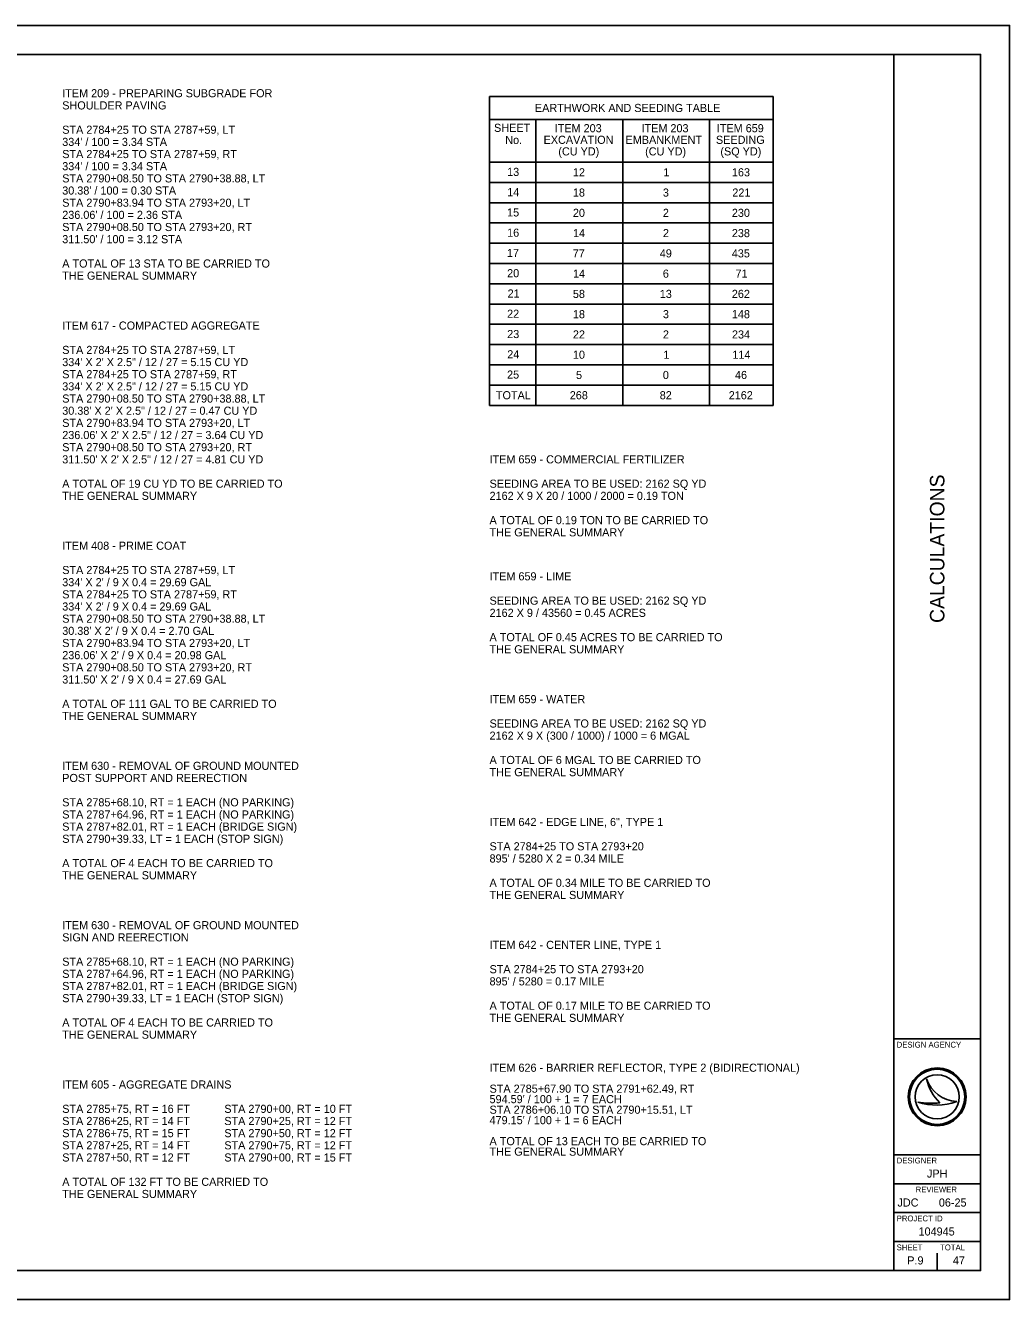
# Model space of a CAD drawing. Extents: x 0 to 34, y 0 to 22.
# Drawn here: x 17 to 34, y 0 to 22 of the extents above; entities that cross this region are included whole.
import ezdxf

# ---------------------------------------------------------------- set-up
doc = ezdxf.new("R2010")
doc.units = 0
for name, color, linetype in [('SH_Border', 7, 'Continuous'), ('SH_Cut_Line', 7, 'Continuous'), ('SH_Data', 7, 'Continuous'), ('TX_P_1', 7, 'Continuous')]:
    doc.layers.add(name, color=color, linetype=linetype)

msp = doc.modelspace()

# ---------------------------------------------------------------- linework, layer by layer
at = {"layer": 'SH_Border'}
for p, q in [((32, 0.5), (32, 21.5)), ((32, 4.5), (33.5, 4.5)), ((32, 2.5), (33.5, 2.5)), ((32, 2), (33.5, 2)), ((32, 1.5), (33.5, 1.5)), ((32, 1), (33.5, 1))]:
    msp.add_line(p, q, dxfattribs=at)
msp.add_lwpolyline([(1.5, 21.5), (33.5, 21.5), (33.5, 0.5), (1.5, 0.5)], close=True, dxfattribs=at)
at = {"layer": 'SH_Cut_Line'}
msp.add_lwpolyline([(0, 0), (34, 0), (34, 22), (0, 22)], close=True, dxfattribs=at)
at = {"layer": 'SH_Data'}
for p, q in [((32.567, 3.81), (32.567, 3.81)), ((32.417, 3.41), (32.417, 3.41)), ((32.75, 3.5), (32.75, 3.5)), ((33.087, 3.419), (33.087, 3.419)), ((32.375, 0.675), (32.375, 0.675)), ((32.75, 0.5), (32.75, 0.8))]:
    msp.add_line(p, q, dxfattribs=at)
for radius in [0.5, 0.477, 0.477, 0.382]:
    msp.add_circle((32.75, 3.5), radius, dxfattribs=at)
for centre, radius, start, end in [((33.116, 3.998), 0.58, 198.9257, 198.9319), ((33.347, 3.97), 0.796, 191.6379, 191.6421), ((33.116, 3.998), 0.58, 198.9319, 267.1657), ((33.347, 3.97), 0.796, 191.6421, 226.0947), ((32.739, 4.37), 1.013, 251.4576, 290.0832), ((32.648, 4.654), 1.266, 259.4964, 259.4995), ((32.739, 4.37), 1.013, 251.4527, 251.4576), ((32.648, 4.654), 1.266, 259.4995, 276.6672)]:
    msp.add_arc(centre, radius, start, end, dxfattribs=at)
at = {"layer": 'TX_P_1'}
for p, q in [((29.917, 20.776), (25.017, 20.776)), ((25.017, 20.776), (25.017, 15.44)), ((29.917, 20.776), (29.917, 15.44)), ((29.917, 20.376), (25.017, 20.376)), ((25.817, 20.376), (25.817, 15.44)), ((27.317, 20.376), (27.317, 15.44)), ((28.817, 20.376), (28.817, 15.44)), ((29.917, 19.64), (25.017, 19.64)), ((29.917, 19.29), (25.017, 19.29)), ((29.917, 18.94), (25.017, 18.94)), ((29.917, 18.59), (25.017, 18.59)), ((29.917, 18.24), (25.017, 18.24)), ((29.917, 17.89), (25.017, 17.89)), ((29.917, 17.54), (25.017, 17.54)), ((29.917, 17.19), (25.017, 17.19)), ((29.917, 16.84), (25.017, 16.84)), ((29.917, 16.49), (25.017, 16.49)), ((29.917, 16.14), (25.017, 16.14)), ((29.917, 15.79), (25.017, 15.79)), ((29.917, 15.44), (25.017, 15.44))]:
    msp.add_line(p, q, dxfattribs=at)

# ---------------------------------------------------------------- texts
at = {"layer": 'SH_Data'}
msp.add_text('CALCULATIONS', height=0.25, rotation=90, dxfattribs=at).set_placement((32.875, 11.683))
for s, height, p in [('DESIGN AGENCY', 0.1, (32.05, 4.35)), ('DESIGNER', 0.1, (32.05, 2.35)), ('JPH', 0.14, (32.573, 2.105)), ('REVIEWER', 0.1, (32.378, 1.85)), ('JDC', 0.14, (32.064, 1.605)), ('06-25', 0.14, (32.779, 1.605)), ('PROJECT ID', 0.1, (32.05, 1.35)), ('104945', 0.14, (32.428, 1.105)), ('SHEET', 0.1, (32.05, 0.85)), ('TOTAL', 0.1, (32.8, 0.85)), ('P.9', 0.14, (32.233, 0.605)), ('47', 0.14, (33.021, 0.605))]:
    msp.add_text(s, height=height, dxfattribs=at).set_placement(p)
at = {"layer": 'TX_P_1'}
for s, p in [('ITEM 209 - PREPARING SUBGRADE FOR', (17.635, 20.76)), ('SHOULDER PAVING', (17.635, 20.55)), ('EARTHWORK AND SEEDING TABLE', (25.801, 20.506)), ('STA 2784+25 TO STA 2787+59, LT', (17.635, 20.13)), ('SHEET', (25.095, 20.163)), ('ITEM 203', (26.143, 20.156)), ('ITEM 203', (27.643, 20.156)), ('ITEM 659', (28.943, 20.156)), ("334' / 100 = 3.34 STA", (17.635, 19.92)), ('No.', (25.288, 19.953)), ('EXCAVATION', (25.951, 19.956)), ('EMBANKMENT', (27.367, 19.956)), ('SEEDING', (28.928, 19.956)), ('STA 2784+25 TO STA 2787+59, RT', (17.635, 19.71)), ('(CU YD)', (26.205, 19.756)), ('(CU YD)', (27.705, 19.756)), ('(SQ YD)', (29.005, 19.756)), ("334' / 100 = 3.34 STA", (17.635, 19.5)), ('STA 2790+08.50 TO STA 2790+38.88, LT', (17.635, 19.29)), ('13', (25.321, 19.402)), ('12', (26.457, 19.395)), ('1', (28.02, 19.395)), ('163', (29.204, 19.395)), ("30.38' / 100 = 0.30 STA", (17.635, 19.08)), ('14', (25.322, 19.052)), ('18', (26.457, 19.045)), ('3', (28.012, 19.045)), ('221', (29.211, 19.045)), ('STA 2790+83.94 TO STA 2793+20, LT', (17.635, 18.87)), ("236.06' / 100 = 2.36 STA", (17.635, 18.66)), ('15', (25.32, 18.702)), ('20', (26.457, 18.695)), ('2', (28.011, 18.695)), ('230', (29.203, 18.695)), ('STA 2790+08.50 TO STA 2793+20, RT', (17.635, 18.45)), ('16', (25.321, 18.352)), ('14', (26.459, 18.345)), ('2', (28.012, 18.345)), ('238', (29.203, 18.345)), ("311.50' / 100 = 3.12 STA", (17.635, 18.24)), ('17', (25.318, 18.002)), ('77', (26.454, 17.995)), ('49', (27.958, 17.995)), ('435', (29.202, 17.995)), ('A TOTAL OF 13 STA TO BE CARRIED TO', (17.635, 17.82)), ('THE GENERAL SUMMARY', (17.635, 17.61)), ('20', (25.321, 17.652)), ('14', (26.459, 17.645)), ('6', (28.011, 17.645)), ('71', (29.266, 17.645)), ('21', (25.329, 17.302)), ('58', (26.457, 17.295)), ('13', (27.958, 17.295)), ('262', (29.203, 17.295)), ('22', (25.321, 16.952)), ('18', (26.457, 16.945)), ('3', (28.012, 16.945)), ('148', (29.203, 16.945)), ('ITEM 617 - COMPACTED AGGREGATE', (17.635, 16.748)), ('23', (25.322, 16.602)), ('22', (26.457, 16.595)), ('2', (28.012, 16.595)), ('234', (29.205, 16.595)), ('STA 2784+25 TO STA 2787+59, LT', (17.635, 16.328)), ('24', (25.323, 16.252)), ('10', (26.457, 16.245)), ('1', (28.02, 16.245)), ('114', (29.212, 16.245)), ('334\' X 2\' X 2.5" / 12 / 27 = 5.15 CU YD', (17.635, 16.118)), ('334\' X 2\' X 2.5" / 12 / 27 = 5.15 CU YD', (17.635, 15.698)), ('STA 2784+25 TO STA 2787+59, RT', (17.635, 15.908)), ('25', (25.32, 15.902)), ('5', (26.511, 15.895)), ('0', (28.011, 15.895)), ('46', (29.257, 15.895)), ('STA 2790+08.50 TO STA 2790+38.88, LT', (17.635, 15.488)), ('TOTAL', (25.127, 15.545)), ('268', (26.403, 15.545)), ('82', (27.957, 15.545)), ('2162', (29.149, 15.545)), ('30.38\' X 2\' X 2.5" / 12 / 27 = 0.47 CU YD', (17.635, 15.278)), ('STA 2790+83.94 TO STA 2793+20, LT', (17.635, 15.068)), ('236.06\' X 2\' X 2.5" / 12 / 27 = 3.64 CU YD', (17.635, 14.858)), ('STA 2790+08.50 TO STA 2793+20, RT', (17.635, 14.648)), ('311.50\' X 2\' X 2.5" / 12 / 27 = 4.81 CU YD', (17.635, 14.438)), ('ITEM 659 - COMMERCIAL FERTILIZER', (25.017, 14.438)), ('A TOTAL OF 19 CU YD TO BE CARRIED TO', (17.635, 14.018)), ('SEEDING AREA TO BE USED: 2162 SQ YD', (25.017, 14.018)), ('THE GENERAL SUMMARY', (17.635, 13.808)), ('2162 X 9 X 20 / 1000 / 2000 = 0.19 TON', (25.017, 13.808)), ('A TOTAL OF 0.19 TON TO BE CARRIED TO', (25.017, 13.388)), ('THE GENERAL SUMMARY', (25.017, 13.178)), ('ITEM 408 - PRIME COAT', (17.635, 12.947)), ('STA 2784+25 TO STA 2787+59, LT', (17.635, 12.527)), ('ITEM 659 - LIME', (25.017, 12.418)), ("334' X 2' / 9 X 0.4 = 29.69 GAL", (17.635, 12.317)), ('STA 2784+25 TO STA 2787+59, RT', (17.635, 12.107)), ('SEEDING AREA TO BE USED: 2162 SQ YD', (25.017, 11.998)), ("334' X 2' / 9 X 0.4 = 29.69 GAL", (17.635, 11.897)), ('2162 X 9 / 43560 = 0.45 ACRES', (25.017, 11.788)), ('STA 2790+08.50 TO STA 2790+38.88, LT', (17.635, 11.687)), ("30.38' X 2' / 9 X 0.4 = 2.70 GAL", (17.635, 11.477)), ('A TOTAL OF 0.45 ACRES TO BE CARRIED TO', (25.017, 11.368)), ('STA 2790+83.94 TO STA 2793+20, LT', (17.635, 11.267)), ('THE GENERAL SUMMARY', (25.017, 11.158)), ("236.06' X 2' / 9 X 0.4 = 20.98 GAL", (17.635, 11.057)), ("311.50' X 2' / 9 X 0.4 = 27.69 GAL", (17.635, 10.637)), ('STA 2790+08.50 TO STA 2793+20, RT', (17.635, 10.847)), ('A TOTAL OF 111 GAL TO BE CARRIED TO', (17.635, 10.217)), ('ITEM 659 - WATER', (25.017, 10.297)), ('THE GENERAL SUMMARY', (17.635, 10.007)), ('SEEDING AREA TO BE USED: 2162 SQ YD', (25.017, 9.877)), ('2162 X 9 X (300 / 1000) / 1000 = 6 MGAL', (25.017, 9.667)), ('ITEM 630 - REMOVAL OF GROUND MOUNTED', (17.635, 9.146)), ('A TOTAL OF 6 MGAL TO BE CARRIED TO', (25.017, 9.247)), ('POST SUPPORT AND REERECTION', (17.635, 8.936)), ('THE GENERAL SUMMARY', (25.017, 9.037)), ('STA 2785+68.10, RT = 1 EACH (NO PARKING)', (17.635, 8.516)), ('STA 2787+64.96, RT = 1 EACH (NO PARKING)', (17.635, 8.306)), ('STA 2787+82.01, RT = 1 EACH (BRIDGE SIGN)', (17.635, 8.096)), ('ITEM 642 - EDGE LINE, 6", TYPE 1', (25.017, 8.176)), ('STA 2790+39.33, LT = 1 EACH (STOP SIGN)', (17.635, 7.886)), ('STA 2784+25 TO STA 2793+20', (25.017, 7.756)), ('A TOTAL OF 4 EACH TO BE CARRIED TO', (17.635, 7.466)), ("895' / 5280 X 2 = 0.34 MILE", (25.017, 7.546)), ('THE GENERAL SUMMARY', (17.635, 7.256)), ('A TOTAL OF 0.34 MILE TO BE CARRIED TO', (25.017, 7.126)), ('THE GENERAL SUMMARY', (25.017, 6.916)), ('ITEM 630 - REMOVAL OF GROUND MOUNTED', (17.635, 6.394)), ('SIGN AND REERECTION', (17.635, 6.184)), ('ITEM 642 - CENTER LINE, TYPE 1', (25.017, 6.054)), ('STA 2785+68.10, RT = 1 EACH (NO PARKING)', (17.635, 5.764)), ('STA 2784+25 TO STA 2793+20', (25.017, 5.634)), ('STA 2787+64.96, RT = 1 EACH (NO PARKING)', (17.635, 5.554)), ("895' / 5280 = 0.17 MILE", (25.017, 5.424)), ('STA 2787+82.01, RT = 1 EACH (BRIDGE SIGN)', (17.635, 5.344)), ('STA 2790+39.33, LT = 1 EACH (STOP SIGN)', (17.635, 5.134)), ('A TOTAL OF 0.17 MILE TO BE CARRIED TO', (25.017, 5.004)), ('A TOTAL OF 4 EACH TO BE CARRIED TO', (17.635, 4.714)), ('THE GENERAL SUMMARY', (25.017, 4.794)), ('THE GENERAL SUMMARY', (17.635, 4.504)), ('ITEM 626 - BARRIER REFLECTOR, TYPE 2 (BIDIRECTIONAL)', (25.017, 3.933)), ('ITEM 605 - AGGREGATE DRAINS', (17.635, 3.643)), ("594.59' / 100 + 1 = 7 EACH", (25.017, 3.39)), ('STA 2785+67.90 TO STA 2791+62.49, RT', (25.017, 3.571)), ('STA 2785+75, RT = 16 FT', (17.635, 3.223)), ('STA 2790+00, RT = 10 FT', (20.435, 3.223)), ('STA 2786+06.10 TO STA 2790+15.51, LT', (25.017, 3.208)), ('STA 2786+25, RT = 14 FT', (17.635, 3.013)), ('STA 2790+25, RT = 12 FT', (20.435, 3.013)), ("479.15' / 100 + 1 = 6 EACH", (25.017, 3.027)), ('STA 2786+75, RT = 15 FT', (17.635, 2.803)), ('STA 2790+50, RT = 12 FT', (20.435, 2.803)), ('STA 2787+25, RT = 14 FT', (17.635, 2.593)), ('STA 2790+75, RT = 12 FT', (20.435, 2.593)), ('A TOTAL OF 13 EACH TO BE CARRIED TO', (25.017, 2.665)), ('STA 2787+50, RT = 12 FT', (17.635, 2.383)), ('STA 2790+00, RT = 15 FT', (20.435, 2.383)), ('THE GENERAL SUMMARY', (25.017, 2.484)), ('A TOTAL OF 132 FT TO BE CARRIED TO', (17.635, 1.963)), ('THE GENERAL SUMMARY', (17.635, 1.753))]:
    msp.add_text(s, height=0.14, dxfattribs=at).set_placement(p)

doc.saveas('drawing.dxf')
